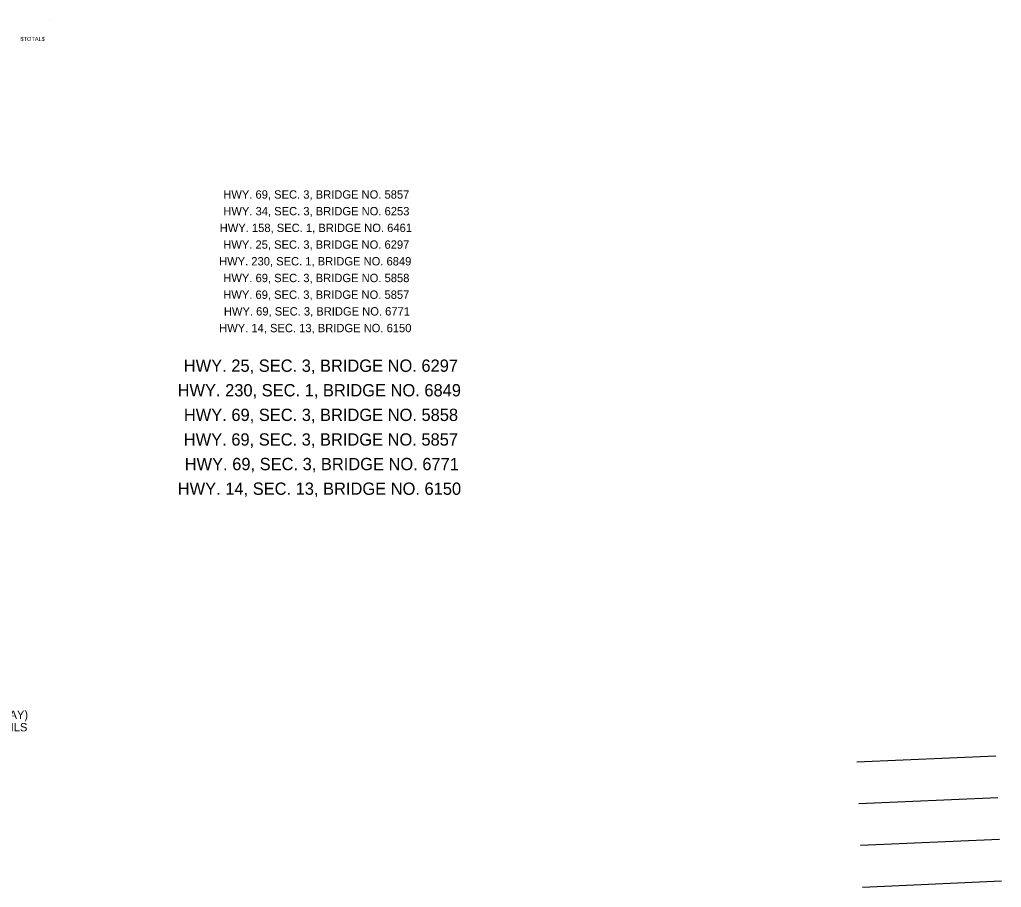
# Model space of a CAD drawing. Extents: x 1926586 to 1930787, y 596452 to 599566.
# Drawn here: x 1929376 to 1930787, y 596452 to 597699 of the extents above; entities that cross this region are included whole.
import ezdxf

# ---------------------------------------------------------------- set-up
doc = ezdxf.new("R2010")
doc.units = 0
for name, color, linetype in [('BR_Pr_Bent_CL', 7, 'Continuous'), ('Default', 7, 'Continuous'), ('R_Border', 7, 'Continuous'), ('R_Border Prem', 7, 'Continuous')]:
    doc.layers.add(name, color=color, linetype=linetype)

msp = doc.modelspace()

# ---------------------------------------------------------------- linework, layer by layer
at = {"layer": 'BR_Pr_Bent_CL'}
for p, q in [((1930779.3, 596640.3), (1930579.5, 596631.6)), ((1930781.9, 596580.4), (1930582.1, 596571.7)), ((1930784.5, 596520.4), (1930584.7, 596511.8)), ((1930787.1, 596460.5), (1930587.3, 596451.8))]:
    msp.add_line(p, q, dxfattribs=at)
at = {"layer": 'R_Border Prem'}
msp.add_line((1929418.3, 597699), (1929418.3, 597699), dxfattribs=at)

# ---------------------------------------------------------------- texts
at = {"layer": 'Default'}
for s, height, p in [('HWY. 69, SEC. 3, BRIDGE NO. 5857', 12, (1929668.4, 597441.7)), ('HWY. 34, SEC. 3, BRIDGE NO. 6253', 12, (1929668.5, 597417.7)), ('HWY. 158, SEC. 1, BRIDGE NO. 6461', 12, (1929663.3, 597393.7)), ('HWY. 25, SEC. 3, BRIDGE NO. 6297', 12, (1929668.4, 597369.7)), ('HWY. 230, SEC. 1, BRIDGE NO. 6849', 12, (1929662.4, 597345.7)), ('HWY. 69, SEC. 3, BRIDGE NO. 5858', 12, (1929668.5, 597321.7)), ('HWY. 69, SEC. 3, BRIDGE NO. 5857', 12, (1929668.4, 597297.7)), ('HWY. 69, SEC. 3, BRIDGE NO. 6771', 12, (1929669.3, 597273.7)), ('HWY. 14, SEC. 13, BRIDGE NO. 6150', 12, (1929662.5, 597249.7)), ('HWY. 25, SEC. 3, BRIDGE NO. 6297', 17.682, (1929611.7, 597192.8)), ('HWY. 230, SEC. 1, BRIDGE NO. 6849', 17.682, (1929602.8, 597157.5)), ('HWY. 69, SEC. 3, BRIDGE NO. 5858', 17.682, (1929611.8, 597122.1)), ('HWY. 69, SEC. 3, BRIDGE NO. 5857', 17.682, (1929611.7, 597086.7)), ('HWY. 69, SEC. 3, BRIDGE NO. 6771', 17.682, (1929613, 597051.4)), ('HWY. 14, SEC. 13, BRIDGE NO. 6150', 17.682, (1929603, 597016))]:
    msp.add_text(s, height=height, rotation=360, dxfattribs=at).set_placement(p)
at = {"layer": 'R_Border'}
for s, p in [('ADVANCE WARNING (2 LANE ROADWAY)', (1929070.4, 596694)), ('MAINTENANCE OF TRAFFIC DETAILS', (1929099.7, 596676))]:
    msp.add_text(s, height=12, rotation=360, dxfattribs=at).set_placement(p)
at = {"layer": 'R_Border Prem'}
msp.add_text('$TOTAL$', height=5.86, rotation=360, dxfattribs=at).set_placement((1929376.8, 597668.3))

doc.saveas('drawing.dxf')
